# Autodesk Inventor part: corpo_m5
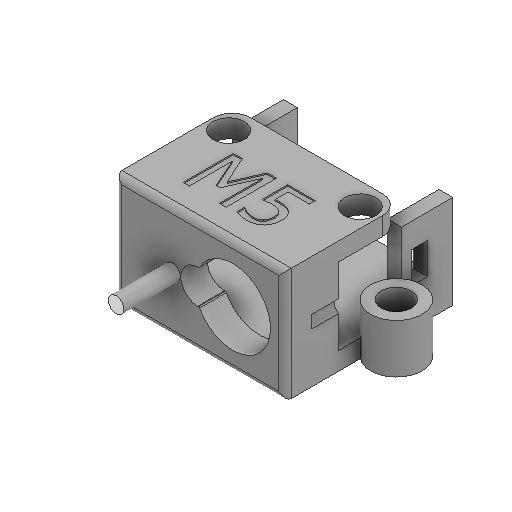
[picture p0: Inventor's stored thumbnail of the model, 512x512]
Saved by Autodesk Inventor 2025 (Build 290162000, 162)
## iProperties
Created: 2021-06
Part Number: corpo_m5
Material: Plastica ABS
Document SubType Name: Modeling
Designer: Ryzen5700u
Density: 1.06 g/cm^3
Appearance: Default
Author: Ryzen5700u
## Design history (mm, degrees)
feature "Solido1"
node "Solido2"
